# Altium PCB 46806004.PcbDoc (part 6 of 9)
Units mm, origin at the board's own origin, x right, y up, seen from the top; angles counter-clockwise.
Board outline 130 x 105 mm, 8 copper layers (Top Layer, P1-GND, L1-Signal, L2-Signal, L3-Signal, L4-Signal, P2-GND, Bottom Layer), stack 1.63 mm thick; 796 components, 496 nets, 2808 pads, 1195 vias.
Unrouted connection lines stored in the file: 1.
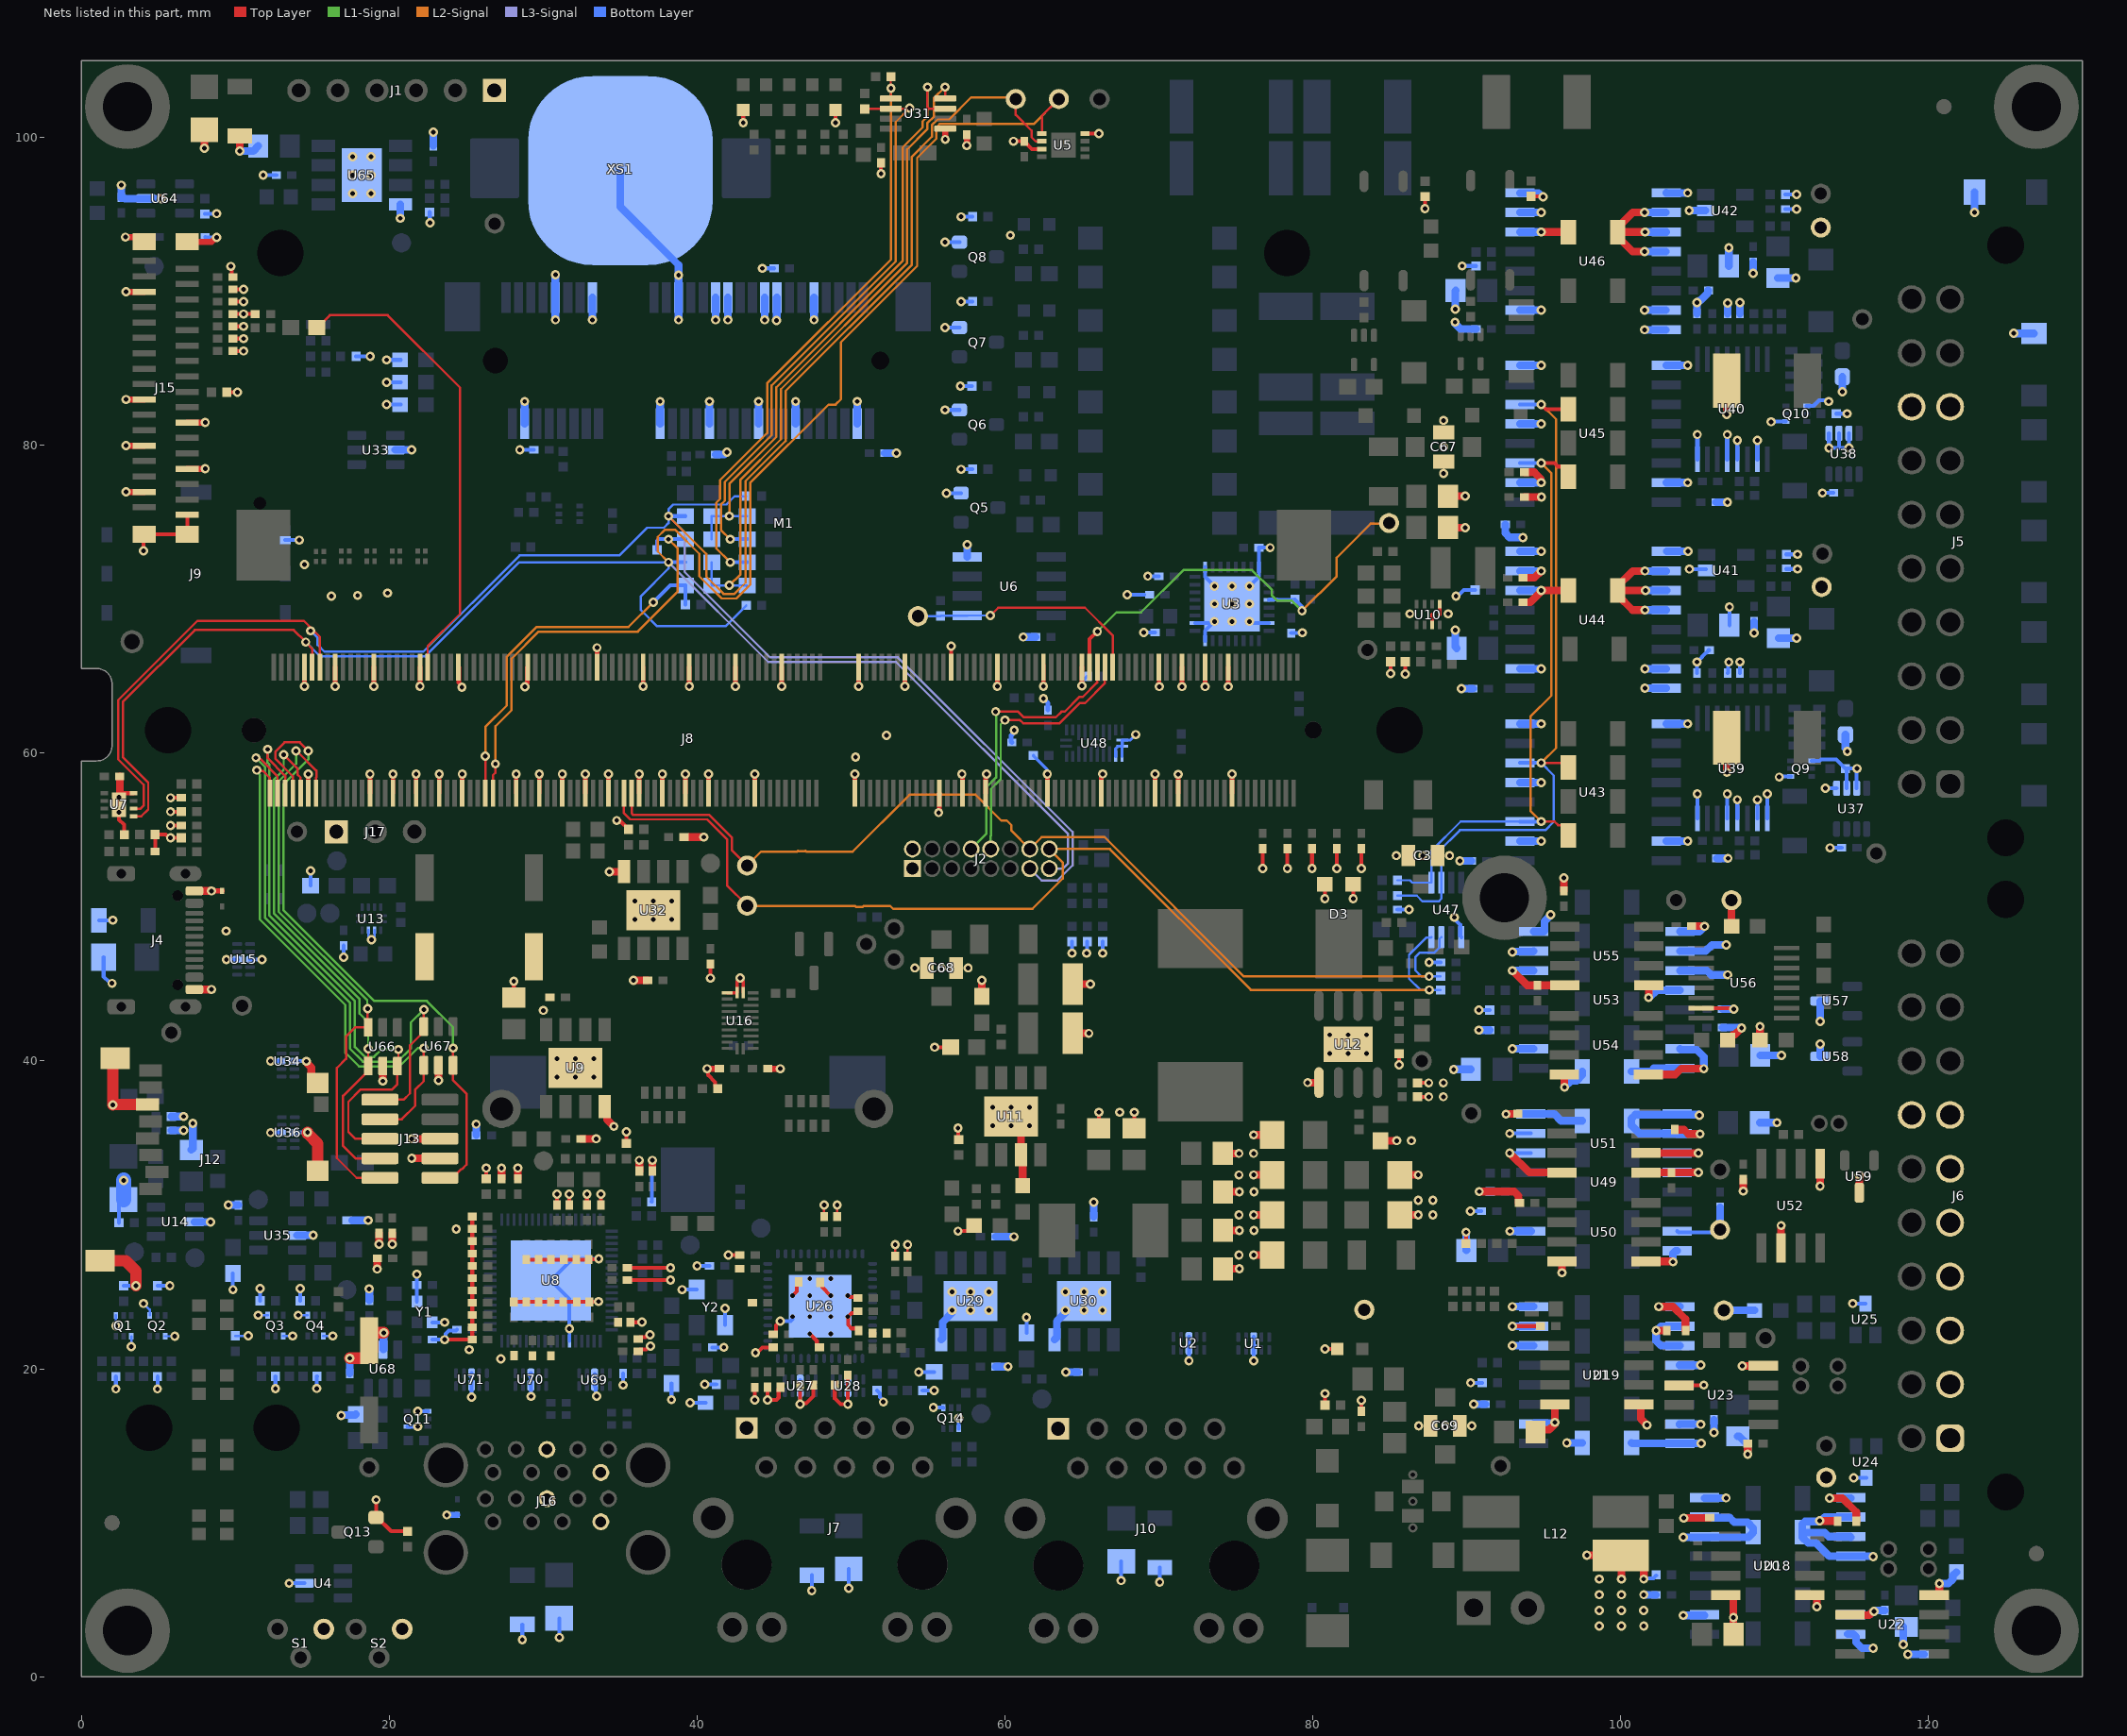
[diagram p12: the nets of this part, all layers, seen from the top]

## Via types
v1: diameter 0.6, hole 0.3, Top Layer to Bottom Layer, tented both sides, 1130 vias
v2: diameter 0.6, hole 0.3, Top Layer to Bottom Layer, 53 vias
v3: diameter 0.3, hole 0.3, Top Layer to Bottom Layer, 12 vias

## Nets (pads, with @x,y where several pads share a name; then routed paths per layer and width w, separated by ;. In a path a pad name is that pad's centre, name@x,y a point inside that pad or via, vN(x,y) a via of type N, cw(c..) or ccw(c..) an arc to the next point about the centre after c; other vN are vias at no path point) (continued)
GND: C2.1 C3.2 C4.1 C5.1 C6.1 C7.1 C8.1 C9.1 C10.1 C11.1 C12.1 C13.1 C14.1 C15.1 C16.1 C17.1 C18.1 C19.1 C20.2 C21.1 C22.1 C23.1 C24.1 C25.1 C26.1 C27.2 C28.1 C29.1 C30.1 C31.1 C32.1 C33.1 C34.2 C35.1 C36.1 C37.1 C38.1 C39.1 C40.1 C41.2 C42.1 C43.1 C44.1 C45.1 C46.1 C47.1 C48.2 C49.2 C50.1 C51.1 C52.1 C53.1 C54.2 C55.2 C56.1 C57.1 C58.1 C59.2 C60.2 C61.1 C62.1 C63.1 C64.1 C65.1 C66.1 C67.2 C68.2 C69.2 C70.1 C71.1 C72.1 C73.1 C74.1 C75.1 C76.1 C77.1 C78.1 C79.1 C81.2 C84.2 C86.1 C88.1 C89.1 C91.1 C92.1 C94.1 C95.1 C96.1 C97.2 C98.1 C99.1 C100.2 C101.2 C102.1 C103.2 C104.1 C106.1 C107.1 C108.1 C109.1 C111.1 C114.1 C115.1 C116.1 C117.2 C118.2 C119.2 C120.2 C133.1 C134.1 C135.1 C136.1 C137.1 C138.1 C139.1 C140.1 C141.1 C142.1 C143.1 C144.1 C145.1 C146.1 C147.1 C148.1 C149.1 C150.1 C151.1 C152.1 C153.1 C154.1 C155.1 C156.1 C157.1 C158.1 C159.1 C160.1 C161.1 C162.1 C163.1 C164.1 C165.1 C166.1 C167.1 C168.2 C169.2 C170.1 C171.1 C172.1 C173.1 C174.1 C175.1 C176.1 C177.1 C178.1 C179.1 C180.1 C181.1 C182.1 C207.1 C208.1 C209.1 C210.2 C211.2 C212.1 C213.1 C214.1 C215.1 C216.1 C217.1 C218.2 C219.2 C220.2 C226.1 C227.2 C228.2 C229.2 C239.1 C240.1 C241.1 C242.1 C243.1 C244.1 C245.1 C246.1 C247.1 C248.1 C249.1 C250.1 C251.1 C252.1 C253.1 C255.2 C257.1 C258.1 D3.1 D3.2 D4.2 D6.2 D18.2 D23.2 D26.2 D31.1 D32.2 J1.1 J2.1 J2.2 J4.A1/B12 J4.B1/A12 J5.15 J5.16 J7.1 J8.4 J8.9 J8.15 J8.18 J8.21 J8.26 J8.27 J8.29 J8.34 J8.35 J8.37 J8.40 J8.43 J8.50 J9.C5 J10.1 J12.6 J12.10 J12.11 J12.12 J12.13 J13.3 J13.5 J15.1 J15.4 J15.7 J15.10 J15.13 J15.16 J15.30 J15.SH1 J15.SH2 J15.SH3 J15.SH4 J16.L4 J16.L7 J16.U4 J16.U7 J17.1 L12.3 M1.10 M1.11 M1.18 M1.27 M1.28 M1.33 M1.39 M1.40 M1.45 M1.50 M1.51 M1.65 M1.68 M1.71 M1.77 M1.83 M1.86 M1.89 M1.97 M1.98 M1.103 M1.109 M1.110 M1.115 M1.122 M1.127 M1.134 M1.145 M1.146 M1.158 M1.167 M1.170 M1.173 M1.179 M1.182 M1.194 M1.195 M1.204 M1.209 M1.223 M1.224 M1.229 M1.230 M1.236 M1.242 M1.243 Q1.1 Q1.4 Q2.1 Q2.4 Q3.1 Q3.4 Q4.1 Q4.4 Q5.2 Q6.2 Q7.2 Q8.2 Q11.1 Q11.4 Q13.2 Q14.1 Q14.4 R3.2 R7.1 R20.2 R21.2 R26.1 R27.1 R29.2 R31.2 R32.1 R33.1 R34.1 R38.1 R40.1 R46.1 R49.1 R52.1 R54.1 R55.2 R57.1 R60.1 R62.1 R63.1 R66.2 R67.1 R70.1 R71.1 R74.1 R75.1 R78.1 R79.1 R81.1 R82.1 R84.1 R88.1 R89.1 R106.1 R107.1 R108.1 R109.1 R114.1 R116.1 R118.1 R122.2 R128.2 R130.2 R131.2 R150.1 R156.2 R176.1 R178.1 R185.1 R188.1 R192.1 R197.1 R198.1 R199.1 R202.1 R205.1 R206.1 R212.1 R214.2 R216.1 R236.1 R240.1 R244.2 R250.2 R256.1 R262.1 R263.1 R266.2 R268.2 R272.2 R273.1 S1.2 S2.2 U1.3 U1.8 U2.3 U2.8 U3.2 U3.9 U3.16 U3.23 U3.32 U3.33 U4.2 U5.4 U5.7 U6.4 U7.4 U7.9 U8.40 U8.69 U9.8 U9.9 U10.3 U10.5 U11.7 U11.9 U12.1 U12.9 U13.10 U13.11 U14.2 U15.3 U15.8 U16.11 U16.12 U16.13 U18.2 U18.6 U18.7 U18.8 U19.2 U19.6 U19.7 U19.8 U20.4 U21.4 U26.49 U27.3 U27.8 U28.3 U28.8 U29.8 U29.9 U30.8 U30.9 U31.1 U32.8 U32.9 U33.2 U34.3 U34.8 U35.2 U36.3 U36.8 U43.2 U43.5 U43.8 U44.2 U44.6 U44.7 U44.8 U45.2 U45.5 U45.8 U46.2 U46.6 U46.7 U46.8 U47.1 U48.11 U48.12 U48.13 U48.14 U49.2 U49.6 U49.7 U49.8 U50.4 U51.4 U53.2 U53.6 U53.7 U53.8 U54.4 U55.4 U64.2 U65.8 U65.9 U66.2 U67.2 U68.2 U69.3 U69.8 U70.3 U70.8 U71.3 U71.8 X1.1 XS1.1 Y1.2 Y1.4 Y2.2 Y2.4 | length 541.2
  Top Layer w0.15: C138.1@48.25,29.9 v1(48.25,30.65) ; C151.1@49.1,29.9 v1(49.1,30.65) ; C153.1@52.874,27.318 v1(52.874,28.068) ; C137.1@53.674,27.318 v1(53.674,28.068)
  Top Layer w0.2: U16.13@41.95,44.425 42.575,44.425 U16.12@42.6,44.45 42.6,45.2 v1(42.8,45.4) 43,45.2 U16.11@43,44.45
  Top Layer w0.25: v1(2.45,56.15) 2.45,55.675 2.775,55.35 2.775,54.725 R7.1@2.8,54.7 ; U7.9@2.675,57.225 2.525,57.225 v1(2.45,57.15) 2.45,57.4 U7.4@3.4,57.4 ; v1(4.05,73.142) 4.05,74.197 J15.SH2@4.081,74.228 J15.SH1@6.881,74.228 J15.1@6.881,75.478 ; C100.2@4.8,53.613 R52.1@4.8,54.713 5.492,54.713 5.705,54.5 v1(5.8,54.5) R54.1@6.5,54.5 ; v1(5.8,55.3) C101.2@6.5,55.3 ; v1(5.8,56.2) R57.1@6.5,56.2 ; v1(5.8,57.1) C103.2@6.5,57.1 ; R199.1@9.45,83.45 v1(10.15,83.45) ; v1(9.718,91.626) 9.784,91.56 9.784,90.994 C250.1@9.85,90.928 ; C247.1@9.85,86.128 v1(10.55,86.128) ; C249.1@9.85,86.928 v1(10.55,86.928) ; C251.1@9.85,87.728 v1(10.55,87.728) ; C248.1@9.85,88.528 v1(10.55,88.528) C245.1@11.3,88.528 ; C246.1@9.85,89.328 v1(10.55,89.328) ; C252.1@9.85,90.128 v1(10.55,90.128) ; v1(19.15,11.5) Q13.2@19.15,10.35 19.225,10.35 20.125,9.45 R263.1@21.2,9.45 ; v1(23.6,21.9) C49.2@25.4,21.9 C46.1@25.4,22.7 C40.1@25.4,23.5 C36.1@25.4,24.3 C50.1@25.4,25.1 C26.1@25.4,25.9 C53.1@25.4,26.7 C33.1@25.4,27.5 C30.1@25.4,28.3 C44.1@25.4,29.1 C47.1@25.4,29.9 ; M1.50@24.5,65.6 M1.50@24.525,65.575 ; 24.525,64.587 24.725,64.387 v1(24.725,64.293) ; R21.2@26.3,32.35 v1(26.3,33.05) ; C61.1@28.095,44.13 v1(28.095,45.182) ; C25.1@28.1,24.35 C29.1@28.9,24.35 C54.2@29.7,24.35 C35.1@30.5,24.35 C32.1@31.3,24.35 C42.1@32.2,24.35 C38.1@33,24.35 ; C61.1@28.21,44.13 C61.1@28.215,44.125 ; v1(28.825,64.31) 28.825,64.405 v1@28.975,64.555 ; C37.1@28.9,27.1 C31.1@29.7,27.1 C34.2@30.5,27.1 C24.1@32.95,27.1 32.974,27.124 33.592,27.124 v1(33.616,27.147) ; M1.68@28.975,65.575 M1.68@29,65.6 ; C56.1@30.9,30.65 v1(30.9,31.35) ; C60.2@31.7,30.65 v1(31.7,31.35) ; C57.1@32.85,30.65 v1(32.85,31.35) ; C38.1@33.012,24.362 33.014,24.364 33.595,24.364 v1(33.61,24.379) ; C52.1@33.75,30.65 v1(33.75,31.35) ; v1(34.78,55.628) 34.847,55.561 35.039,55.561 R150.1@35.55,55.05 ; R26.1@35.402,34.651 35.404,34.653 v1(35.404,35.4) ; C20.2@35.477,25.775 v1(38.275,25.775) ; C18.1@35.477,26.575 v1(38.275,26.575) ; C62.1@35.679,23.03 v1@36.412,23.03 ; C59.2@36.179,21.156 36.298,21.275 36.705,21.275 36.916,21.486 v1(36.975,21.486) ; C55.2@36.179,21.956 36.298,22.075 36.67,22.075 36.746,22.15 36.883,22.15 v1(36.95,22.217) ; v1(40.65,39.5) 40.702,39.448 40.702,39.098 41.175,38.625 41.175,38.375 R272.2@41.35,38.2 ; v1(40.865,45.385) C176.1@40.865,46.3 ; v1(42.029,27.4) C141.1@42.85,27.4 ; C154.1@42.775,26.503 C154.1@42.813,26.466 ; v1(43,100.95) D18.2@43,101.775 ; C147.1@43.475,24.425 C147.1@43.6,24.3 ; v1(43.75,17.979) C160.1@43.75,18.8 ; v1(43.8,21.05) 43.895,21.05 44.245,21.4 C146.1@44.95,21.4 ; C162.1@44.575,18.803 v1(44.575,17.982) 45.153,17.982 45.299,18.128 45.299,18.678 C164.1@45.424,18.803 ; C143.1@44.95,22.25 45,22.25 45.125,22.375 45.125,22.825 v1(45.4,23.1) ; v3(46.2,24.753) 46.2,24.767 46.475,25.042 46.475,25.525 C150.1@46.6,25.65 ; v1(46.688,17.708) v1@46.694,17.714 ; C136.1@46.7,18.95 46.694,18.944 v1@46.694,17.714 ; v3@47.331,22.265 47.783,21.813 47.783,21.525 47.908,21.4 C155.1@47.95,21.4 ; C133.1@47.55,18.95 47.55,18.232 47.084,17.767 46.747,17.767 v1@46.694,17.714 ; C140.1@48,25.625 48.125,25.5 48.125,25.307 v3@48.669,24.763 ; C148.1@48.95,18.95 48.95,18.083 49.325,17.708 v1(49.8,17.708) C152.1@49.8,19.6 ; v1(49,100.95) D6.2@49,101.775 ; v3(49.8,23.396) 49.81,23.387 49.81,22.866 50.047,22.628 50.375,22.628 50.5,22.503 C149.1@50.5,22.5 ; v3(49.8,24.753) 49.814,24.753 49.907,24.66 50.34,24.66 C145.1@50.4,24.6 ; v3@49.81,23.406 50.029,23.625 50.275,23.625 C134.1@50.4,23.75 ; v1(51.95,97.65) C173.1@51.95,98.35 ; v1(55.425,40.9) R32.1@56.475,40.9 ; M1.167@55.75,57.4 M1.167@55.76,57.41 ; M1.170@56.5,65.6 v1(56.5,66.95) v1@56.525,66.925 ; v1(56.95,28.95) 57.65,28.95 C81.2@58,29.3 ; v1(56.954,35.646) 56.977,35.623 56.977,34.923 R40.1@57,34.9 ; v1(60.55,99.75) C14.1@61.25,99.75 61.75,99.25 U5.7@62.4,99.25 ; M1.194@62.5,65.6 M1.194@62.5,65.739 ; U5.4@65.2,100.25 v1(66.1,100.25) ; C95.1@66.1,35.625 v1(66.1,36.675) ; C94.1@68.4,35.625 v1(68.4,36.675) ; M1.224@70,65.6 M1.224@70.013,65.588 ; v1@70.013,64.337 v1(70.025,64.325) ; v1(76.75,52.506) 76.75,53.45 ; v1(78.35,52.506) 78.35,53.45 ; v1(79.95,52.506) 79.95,53.45 ; v1(80.78,50.542) D3.2@80.78,51.486 ; R49.1@80.8,17.65 v1(80.8,18.4) ; v1(80.8,21.3) D4.2@81.575,21.3 ; v1(81.55,52.506) 81.55,53.45 ; v1(82.62,50.542) D3.1@82.62,51.486 ; C97.2@83.15,17.25 v1(83.15,17.95) ; v1(83.15,52.506) 83.15,53.45 ; v1(85.05,65.175) R27.1@85.05,65.912 ; v1(85.6,39.75) R46.1@85.6,40.478 ; v1(86,65.15) R38.1@86,65.95 ; R33.1@86.8,37.678 v1(87.528,37.678) ; R34.1@86.8,38.578 v1(87.528,38.578) ; v1(87.28,95.383) 87.288,95.391 87.288,96.146 R198.1@87.295,96.153 ; U10.3@87.75,68.325 87.75,69 ; 88.25,69 U10.5@88.25,69.675 ; R185.1@89.95,28.15 v1(89.95,28.887) ; v1(92.969,22.774) 92.979,22.784 C120.2@94.788,22.784 ; R197.1@94.175,96.173 94.187,96.162 94.938,96.162 v1(94.95,96.15)
  Top Layer w0.3: v1(14.5,64.35) M1.10@14.5,65.6 ; M1.11@14.75,57.4 v1(14.75,58.65) ; v1(16.5,64.35) M1.18@16.5,65.6 ; M1.27@18.75,57.4 v1(18.75,58.65) ; v1(19,64.35) M1.28@19,65.6 ; M1.33@20.25,57.4 v1(20.25,58.65) ; M1.39@21.75,57.4 v1(21.75,58.65) ; v1(22,64.35) M1.40@22,65.6 ; M1.45@23.25,57.4 v1(23.25,58.65) ; 24.525,64.587 M1.50@24.525,65.575 ; M1.51@24.75,57.4 v1(24.75,58.65) ; M1.65@28.25,57.4 v1(28.25,58.65) ; v1@28.975,64.555 M1.68@28.975,65.575 ; M1.71@29.75,57.4 v1(29.75,58.65) ; M1.77@31.25,57.4 v1(31.25,58.65) ; M1.83@32.75,57.4 v1(32.75,58.65) ; M1.86@33.5,65.6 v1(33.5,66.85) ; M1.89@34.25,57.4 v1(34.25,58.65) ; M1.97@36.25,57.4 v1(36.25,58.65) ; v1(36.5,64.35) M1.98@36.5,65.6 ; M1.103@37.75,57.4 v1(37.75,58.65) ; M1.109@39.25,57.4 v1(39.25,58.65) ; v1(39.5,64.35) M1.110@39.5,65.6 ; M1.115@40.75,57.4 v1(40.75,58.65) ; v1(42.5,64.35) M1.122@42.5,65.6 ; M1.127@43.75,57.4 v1(43.75,58.65) ; v1(45.5,64.35) M1.134@45.5,65.6 ; M1.145@50.25,57.4 v1(50.25,58.65) ; v1(50.5,64.35) M1.146@50.5,65.6 ; v1(53.5,64.35) M1.158@53.5,65.6 ; v1(55.697,56.137) v1(55.697,56.137) 55.7,56.139 55.75,56.139 M1.167@55.75,57.4 ; v1(57.2,58.65) 57.25,58.65 M1.173@57.25,57.4 ; M1.179@58.75,57.4 58.75,58.65 v1(58.8,58.65) ; v1(59.5,64.35) M1.182@59.5,65.6 ; v1(62.5,64.35) M1.194@62.5,65.6 ; M1.195@62.75,57.4 v1(62.75,58.65) ; v1(65,64.375) M1.204@65,65.6 ; M1.209@66.25,57.4 66.25,58.55 v1(66.354,58.654) ; M1.223@69.75,57.4 v1(69.75,58.65) ; v1@70.013,64.337 M1.224@70.013,65.588 ; M1.229@71.25,57.4 v1(71.25,58.625) ; v1(71.5,64.325) M1.230@71.5,65.6 ; v1(73,64.325) M1.236@73,65.6 ; v1(74.5,64.325) M1.242@74.5,65.6 ; M1.243@74.75,57.4 v1(74.75,58.65)
  Top Layer w0.35: v1(8.45,51.05) D32.2@9.15,51.05
  Top Layer w0.4: v1(2.868,93.528) 3.781,93.528 J15.SH3@4.081,93.228 ; v1(2.913,76.978) J15.4@4.081,76.978 ; v1(2.913,79.978) J15.10@4.081,79.978 ; v1(2.913,82.978) J15.16@4.081,82.978 ; v1(2.913,89.978) J15.30@4.081,89.978 ; J15.7@6.881,78.478 v1(8.05,78.478) ; J15.13@6.881,81.478 v1(8.05,81.478) ; J15.SH4@6.881,93.228 8.474,93.228 8.746,93.5 v1(8.8,93.5) ; v1(40.65,39.5) C114.1@41.45,39.5 ; C111.1@44.6,39.5 v1(45.4,39.5) ; v1(56.12,99.875) U31.1@56.12,100.575 ; v1(57.525,99.475) C167.1@57.525,100.175
  Top Layer w0.5: U7.9@2.5,57.2 C16.1@2.5,58.5 ; J4.B1/A12@7.35,44.65 v1(8.45,44.65) ; J4.A1/B12@7.35,51.05 v1(8.45,51.05) ; v1(8,99.3) C102.1@8,100.5 ; v1(10.3,99.125) R55.2@10.3,100.1 ; v1(14.625,39.987) 14.644,39.968 14.644,39.874 14.947,39.57 14.947,38.975 15.347,38.575 J12.10@15.363,38.575 ; v1@19.231,26.481 C21.1@19.231,27.181 ; v1(19.35,28.1) C161.1@19.35,28.8 ; v1(19.587,38.7) U66.2@19.587,39.675 ; v1(20.2,28.1) C157.1@20.2,28.8 ; v1(21.47,33.68) J13.3@23.3,33.68 ; v1(21.47,34.95) J13.5@23.3,34.95 ; v1(23.2,38.75) U67.2@23.2,39.725 ; C48.2@27.3,32.35 v1(27.3,33.05) ; C45.1@28.35,32.35 v1(28.35,33.05) ; C66.1@32.465,34.95 v1(33.454,34.95) ; U9.8@34.005,37.05 34.156,36.899 34.156,36.194 v1(34.6,35.75) ; v1(34.315,52.3) U32.8@35.26,52.3 ; v1(35.875,45.25) C174.1@36.79,45.25 ; C65.1@36.25,32.85 v1(36.25,33.55) ; C64.1@37.1,32.85 v1(37.1,33.55) ; 39.5,54.55 v1(40.445,54.55) ; R29.2@58.5,44.2 v1(58.5,45.25) ; C84.2@61.15,31.9 61.15,33.785 U11.7@61.035,33.9 61.035,35.235 v2(61.6,35.8) ; C73.1@64.4,41.8 v1(65.45,41.8) ; C77.1@64.4,45 v1(65.55,45) ; C92.1@74.15,34 v1(75.2,34) ; C96.1@74.175,26.5 v1(75.225,26.5) ; C98.1@74.175,29 v1(75.225,29) ; C99.1@74.175,31.5 v1(75.225,31.5) ; v1(76.15,27.4) C70.1@77.35,27.4 ; v1(76.15,30) C72.1@77.35,30 ; v1(76.15,32.6) C75.1@77.35,32.6 ; v1(76.15,35.2) C76.1@77.35,35.2 ; v1(79.667,38.6) U12.1@80.395,38.6 ; R31.2@84.4,34.828 v1(85.45,34.828) ; C78.1@85.65,30 v1(86.85,30) ; C79.1@85.65,32.6 v1(86.85,32.6) ; C71.1@88.775,76.7 v1(89.9,76.7) ; C74.1@88.777,74.654 v1(89.902,74.654) ; v1@90.832,31.521 93.079,31.521 93.372,31.228 93.372,30.785 C219.2@93.422,30.785 ; v1(92.55,36.55) 92.567,36.567 93.305,36.567 C220.2@93.322,36.585 ; v1(92.791,34.027) 94.06,32.758 U51.4@96.191,32.758 ; v1(92.969,45.875) 92.969,45.872 93.917,44.924 C229.2@94.594,44.924 U55.4@96.37,44.924 ; C88.1@93.65,69.8 94.134,69.8 94.812,70.478 94.812,70.55 v1(94.831,70.569) 96.594,70.569 R256.1@96.6,70.563 ; C86.1@93.65,71.4 94.392,71.4 v1(94.831,71.839) ; C89.1@93.75,76.65 v1(94.85,76.65) ; C91.1@93.75,78.25 94.387,78.25 94.812,77.825 94.812,77.598 v1(94.831,77.579) ; C116.1@94.475,15.9 94.624,16.049 95.354,16.049 95.712,16.407 95.712,16.506 v1(95.731,16.525) ; v1(94.831,93.862) 94.834,93.859 96.594,93.859 R262.1@96.6,93.853 ; v1@95.72,16.437 U21.4@95.72,17.695 ; v1(96.191,26.245) U50.4@96.191,26.982 ; C228.2@96.3,51.05 v1(96.3,51.9) ; U54.4@96.347,39.124 96.347,38.303 v1(96.35,38.3) ; v1(97.8,7.9) 99.99,7.9 L12.3@100.01,7.88 ; v1(100.05,6.35) 100.05,7.84 L12.3@100.01,7.88 ; v1(101.5,6.35) 101.5,7.14 100.76,7.88 L12.3@100.01,7.88 ; v1(104.099,10.309) v1(104.099,10.309) C119.2@105.78,10.31 ; C115.1@107.325,2.71 v1(107.325,3.848) 107.325,5.141 U20.4@107.439,5.255
  Top Layer w0.75: J12.12@1.213,27.025 2.875,27.025 3.55,26.35 v1(3.55,25.4) ; v1(2.05,37.15) 2.05,40.012 J12.11@2.213,40.175 ; v1@2.085,37.185 J12.6@4.303,37.185 ; v1(14.7,35.375) 14.7,35.3 15.363,34.637 J12.13@15.363,32.875 ; v1(17.45,20.7) 18.481,20.7 18.919,21.137 18.919,22.35 v1(19.65,22.35)
  Bottom Layer w0.15: v1(2.25,22.8) Q1.1@2.25,23.475 ; v1(3.25,21.45) Q1.4@3.25,22.125 ; v1(4.05,24.25) 4.45,23.85 Q2.1@4.45,23.475 ; Q2.4@5.45,22.125 v1(6.075,22.125) ; R82.1@10,22.15 v1(10.85,22.15) ; v1(11.489,23.49) Q3.1@12.114,23.49 ; Q3.4@13.114,22.14 v1(13.739,22.14) ; v1(14.089,23.49) Q4.1@14.714,23.49 ; Q4.4@15.714,22.14 v1(16.339,22.14) ; U13.11@18.65,48.5 18.65,48.075 v1(18.85,47.875) 19.05,48.075 U13.10@19.05,48.5
  Bottom Layer w0.2: U8.40@31.711,21.8 v1(31.711,22.606) ; R273.1@61.85,59.85 61.85,59.826 62.75,58.926 v1(62.75,58.65) ; v1(65,64.375) 65.077,64.452 65.077,64.72 R84.1@65.35,64.993 ; U48.14@67.2,59.8 67.2,60.3 67.35,60.45 U48.12@67.625,60.45 ; U48.13@67.6,59.8 67.6,60.425 U48.12@67.625,60.45 ; v1(68.492,61.208) 68.5,61.2 68.15,60.85 U48.11@67.625,60.85 U48.12@67.625,60.45
  Bottom Layer w0.25: R66.2@1.15,49.15 v1(2.05,49.15) ; C109.1@1.45,46.75 1.45,45.5 1.833,45.117 1.933,45.117 v1(2,45.05) ; v1(2.25,18.7) R70.1@2.25,19.5 ; R62.1@2.45,29.5 2.45,30.7 C107.1@2.75,31 ; R67.1@2.75,25.4 v1(3.55,25.4) ; v1(2.868,93.528) C244.1@4.05,93.528 ; v1(4.95,18.7) R74.1@4.95,19.5 ; R71.1@4.95,25.4 v1(5.75,25.4) ; R206.1@8.031,95.028 8.042,95.039 8.789,95.039 v1(8.8,95.05) ; C243.1@8.05,93.528 8.064,93.514 8.786,93.514 v1(8.8,93.5) ; v1(9.42,46.6) U15.3@10.17,46.6 ; v1(9.85,25.15) R156.2@9.85,26.2 ; U15.8@10.987,46.6 v1(11.738,46.6) ; R75.1@11.614,24.415 v1(11.614,25.215) ; v1(11.817,97.547) C239.1@12.675,97.547 ; v1(12.3,35.35) U36.8@13.008,35.35 ; v1(12.3,40) 12.971,40 U34.8@12.983,39.987 ; v1(12.614,18.715) R78.1@12.614,19.515 ; J9.C5@13.245,73.84 v1(14.153,73.84) ; v1(13.5,6.075) U4.2@14.495,6.075 ; U34.3@13.8,39.987 v1(14.625,39.987) ; U36.3@13.825,35.35 13.838,35.363 14.687,35.363 v1(14.7,35.375) ; R79.1@14.214,24.415 v1(14.214,25.215) ; R60.1@14.9,51.4 v1(14.9,52.35) ; v1(15.301,18.732) 15.308,18.739 15.308,19.508 R81.1@15.314,19.515 ; v1(17.05,46.75) C106.1@17.05,47.497 ; R202.1@17.85,85.775 v1(18.772,85.775) ; v1(19.84,82.65) C177.1@20.7,82.65 C177.1@20.75,82.65 ; v1(19.84,84.1) C178.1@20.7,84.1 C178.1@20.75,84.1 ; v1(19.84,85.55) C179.1@20.7,85.55 C179.1@20.75,85.55 ; Q11.1@21.175,16.25 v1(21.85,16.25) ; Y1.4@21.8,24.375 21.8,25.6 v1(21.8,26.15) ; v1(21.861,17.25) Q11.4@22.525,17.25 ; R205.1@22.625,95.15 22.637,95.137 22.637,94.463 v1(22.65,94.45) ; C23.1@22.8,21.9 v1(23.6,21.9) 23.667,21.967 23.667,22.267 23.885,22.485 24.335,22.485 C43.1@24.4,22.55 ; Y1.2@22.8,23.025 v1(23.6,23.025) ; v1(25.35,18.175) U71.3@25.35,18.925 U71.8@25.35,19.742 ; v1(28.49,79.7) C175.1@29.4,79.7 ; v1(28.65,2.4) R214.2@28.65,3.4 ; U70.8@29.2,19.742 U70.3@29.2,18.925 29.213,18.912 29.213,18.226 v1(29.225,18.214) ; v1(31.05,2.55) C257.1@31.05,3.8 ; v1(31.711,22.606) 31.711,24.547 U8.69@30.511,25.747 31.911,27.147 v1(33.616,27.147) ; U69.3@33.35,19.675 U69.8@33.35,18.858 33.416,18.792 33.416,18.288 v1(33.482,18.222) ; v1(35.2,18.95) C28.1@35.2,19.7 ; R212.1@37.05,30.85 37.075,30.875 37.075,33.525 v1(37.1,33.55) ; v1(38.341,18) R20.2@38.341,19.05 ; v1(39.031,25.15) Y2.2@39.975,25.15 ; v1(39.55,17.8) C156.1@40.55,17.8 ; v1(40,26.7) C142.1@40.8,26.7 ; v1@40.511,19 R122.2@41.25,19 ; C139.1@41,21.4 v1@41.739,21.4 ; Y2.4@41.825,22.85 v1(41.825,23.925) ; v1(44.25,91.5) C172.1@45,91.5 ; v1(45.4,23.1) 46.075,23.1 46.2,23.225 v3(46.2,23.396) ; v1(46.688,17.708) 46.694,17.714 46.694,18.452 U27.8@46.7,18.458 U27.3@46.7,19.275 ; v1(47.45,5.6) R131.2@47.45,6.6 ; v1(49.8,17.708) U28.8@49.8,18.458 U28.3@49.8,19.275 ; v1(49.85,5.75) C163.1@49.85,7 ; R268.2@51.7,18.6 51.875,18.425 51.875,18.17 52.1,17.945 v1(52.1,17.85) ; v1(54.4,19.8) R128.2@55.4,19.8 ; R266.2@54.65,18.6 v1(55.4,18.6) ; v1(55.35,17.5) 55.363,17.488 55.987,17.488 Q14.1@56,17.475 ; v1@56.1,93.19 v1(56.104,93.194) 57.043,93.194 Q8.2@57.047,93.199 ; v1(56.108,82.299) Q6.2@57.047,82.299 ; v1(56.108,87.649) Q7.2@57.047,87.649 ; v1@56.208,76.899 Q5.2@57.147,76.899 ; Q14.4@57,16.125 v1(57,16.8) ; v1@57.108,83.849 R107.1@57.847,83.849 ; v1(57.15,78.44) 57.154,78.444 57.893,78.444 R106.1@57.897,78.449 ; v1@57.158,89.349 R108.1@57.897,89.349 ; v1@57.158,94.849 R109.1@57.897,94.849 ; R130.2@61.4,22.35 v1(61.4,23.35) ; v1@64.35,47.011 R118.1@64.35,47.75 ; v1(65.304,47.007) 65.327,47.03 65.327,47.727 R114.1@65.35,47.75 ; v1@66.35,47.011 R116.1@66.35,47.75 ; v1(67.55,6.25) C2.1@67.55,7.5 ; v1(67.95,70.3) 69.05,70.3 ; v1(69.025,67.85) C11.1@69.75,67.85 ; v1(69.275,71.5) C9.1@70,71.5 ; v1@70.025,64.255 v1(70.025,64.325) ; v1(70.05,6.15) R3.2@70.05,7.1 ; v1(71.95,20.533) U2.3@71.95,21.283 U2.8@71.95,22.1 ; U3.2@72.35,68.45 U3.33@73.5,68.45 ; U3.32@73,67.3 73,67.95 U3.33@73.5,68.45 ; U3.9@73,72.1 73,71.45 v2(73.607,70.843) ; v2(73.607,68.557) U3.33@73.5,68.45 ; v2(75.893,68.557) 76,68.45 U3.23@77.15,68.45 ; v2(75.893,70.843) 76.5,71.45 U3.16@76.5,72.1 C13.1@76.5,73.35 v1(77.225,73.35) ; v1(76.162,20.52) U1.3@76.163,21.27 U1.8@76.163,22.087 ; C10.1@78.6,67.8 78.613,67.812 79.312,67.812 v1(79.325,67.825) ; C209.1@85.5,49.845 v1(86.25,49.845) ; v1(87.55,46.4) C216.1@88.3,46.4 ; v1(89.2,49.335) 89.2,49.24 89.575,48.865 89.575,48.125 U47.1@89.65,48.05 ; v1(89.3,70.2) 89.395,70.2 89.795,70.6 R176.1@90.55,70.6 ; v1(89.696,91.648) 89.7,91.653 R178.1@90.6,91.653 ; v1@90.238,30.25 C218.2@90.95,30.25 ; v1(90.25,19.1) R89.1@91,19.1 ; v1@90.788,43.307 R192.1@91.5,43.307 ; v1(90.809,31.521) R188.1@91.522,31.523 ; v1@92.792,34.028 U49.6@94.172,34.028 ; v1@92.792,35.298 U49.7@94.172,35.298 ; v1(101.5,6.35) 101.54,6.39 101.735,6.39 101.75,6.405 102.125,6.405 R88.1@102.3,6.58 ; D26.2@122.985,96.45 D26.2@123.015,96.42 ; v1(125.525,87.275) v1@125.535,87.265
  Bottom Layer w0.3: C213.1@60.45,60.7 60.4,60.75 60.4,61.15 60.6,61.35 v1(60.6,61.5) ; v1(62.5,63.55) 62.8,63.25 C215.1@62.8,62.8
  Bottom Layer w0.4: v1(23.746,10.512) D31.1@24.421,10.512
  Bottom Layer w0.5: C241.1@2.6,96.111 v1(2.6,96.9) ; C241.1@2.611,96.1 2.611,96.05 2.818,96.05 2.84,96.028 v1(5.2,96.028) ; C108.1@5.85,35.5 v1(6.65,35.5) ; R63.1@5.85,36.4 v1(6.65,36.4) ; C104.1@7.15,34.225 7.25,34.325 v1(7.25,35.95) ; U14.2@7.36,29.55 v1(8.4,29.55) ; v1(9.55,30.65) C182.1@10.2,30.65 ; v1(10.3,99.125) 11.175,99.125 C240.1@11.5,99.45 ; U35.2@14.026,28.681 v1(15.066,28.681) ; v1(16.881,16.975) 16.9,16.994 17.775,16.994 R216.1@17.831,17.05 ; C258.1@17.45,19.7 v1(17.45,20.7) ; 17.6,29.65 v1(18.64,29.65) ; v1(18.7,25.2) 18.711,25.189 C253.1@18.711,24.45 ; U68.2@19.611,21.255 19.631,21.274 19.631,22.331 v1(19.65,22.35) ; U33.2@20.405,79.7 v1(21.455,79.7) ; v1(20.725,94.745) U65.8@20.725,95.645 ; C242.1@22.875,99.45 v1(22.875,100.35) ; C39.1@25.65,35.2 v1(25.65,35.9) ; J8.4@28.8,81.4 v1(28.8,82.85) ; v1(30.8,88.15) J8.9@30.8,89.6 v1(30.8,91.091) ; v1(33.2,88.15) J8.15@33.2,89.6 ; XS1.1@35.02,97.85 35.02,95.495 38.8,91.715 v1(38.8,91.05) J8.21@38.8,89.6 v1(38.8,88.15) ; J8.18@37.6,81.4 v1(37.6,82.85) ; J8.26@40.8,81.4 v1(40.8,82.85) ; C171.1@41.2,79.4 41.773,79.4 41.923,79.55 v1(41.95,79.55) ; v1(41.2,88.15) J8.27@41.2,89.6 ; v1(42,88.15) J8.29@42,89.6 ; J8.34@44,81.4 v1(44,82.85) ; v1(44.4,88.15) J8.35@44.4,89.6 ; v1(45.154,88.104) 45.177,88.127 45.177,89.577 J8.37@45.2,89.6 ; J8.40@46.4,81.4 v1(46.4,82.85) ; v1(47.6,88.15) J8.43@47.6,89.6 ; J8.50@50.4,81.4 v1(50.4,82.85) ; C170.1@52.2,79.5 v1(52.95,79.5) ; U29.8@55.86,21.9 55.947,21.987 55.947,23.027 56.565,23.644 v2(56.565,23.8) ; U6.4@57.556,72.751 v1(57.556,73.551) ; C165.1@59.4,20.15 v1(60.2,20.15) ; C158.1@59.4,28.595 60.566,28.595 v1(60.579,28.582) ; v1(61.186,67.546) C15.1@61.986,67.546 ; U30.8@63.23,21.9 63.381,22.051 63.381,22.692 63.384,22.695 63.384,23.093 63.935,23.644 v2(63.935,23.8) ; v1(63.95,19.8) C166.1@64.75,19.8 ; C159.1@65.77,29.88 v1(65.77,30.83) ; v1(89.15,39.45) 89.168,39.468 C226.1@90.275,39.468 ; v1(89.236,88.003) 89.236,87.914 89.597,87.553 C211.2@90.6,87.553 ; v1(89.25,68) 89.25,66.922 C212.1@89.354,66.818 ; v1(89.25,88.85) 89.25,90.028 C214.1@89.275,90.053 ; v1(89.55,53) C207.1@90.3,53 ; v1(89.65,64.2) C210.2@90.4,64.2 ; v1(89.95,28.887) 89.95,27.725 C217.1@89.975,27.7 ; v1(90.45,17.7) C118.2@91.2,17.7 ; v1(90.787,42.005) C227.2@91.5,42.007 ; C208.1@92.5,74.853 92.5,74.3 92.783,74.017 93.633,74.017 v1(93.65,74) ; v1(92.55,36.55) 92.568,36.568 U49.8@94.172,36.568 95.682,36.568 96.132,36.118 R244.2@97.5,36.118 ; v1(92.8,28.948) U49.2@94.172,28.948 ; v1(92.969,45.875) v1(92.969,45.875) 94.349,45.874 U53.6@94.35,45.873 ; v1(92.969,47.075) 93.003,47.109 94.316,47.109 U53.7@94.35,47.143 ; v1@92.97,21.505 U19.6@94.35,21.505 ; v1@92.97,22.775 U19.7@94.35,22.775 ; v1@92.97,24.045 U19.8@94.35,24.045 ; v1(92.969,40.792) U53.2@94.35,40.793 ; U43.2@93.45,54.288 v1@94.83,54.288 ; U43.5@93.45,58.098 v1@94.83,58.098 ; U43.8@93.45,61.908 v1@94.83,61.908 ; U44.2@93.45,65.488 v1(94.831,65.489) ; U44.6@93.45,70.568 v1(94.831,70.569) ; U44.7@93.45,71.838 v1(94.831,71.839) ; U44.8@93.45,73.108 v1(94.831,73.109) ; U45.2@93.45,77.578 v1(94.831,77.579) ; U45.5@93.45,81.388 v1(94.831,81.389) ; U45.8@93.45,85.198 v1(94.831,85.199) ; U46.2@93.45,88.778 v1(94.831,88.779) ; U46.6@93.45,93.858 93.452,93.86 94.829,93.86 v1(94.831,93.862) ; U46.8@93.45,96.398 94.642,96.398 94.89,96.15 v1(94.95,96.15) ; U46.7@93.452,95.13 v1@94.829,95.13 ; U19.2@94.35,16.425 94.4,16.475 95.654,16.475 95.704,16.525 v1(95.731,16.525) ; U53.8@94.35,48.413 95,48.413 95.05,48.463 95.05,49.069 95.456,49.475 v1(95.456,49.502) ; v1(96.35,38.3) 96.771,38.721 97.125,38.721 97.5,39.096 R250.2@97.5,39.318 ; v1(96.5,15.2) R240.1@97.5,15.2 ; v1(101.5,5.33) C117.2@102.29,5.33 ; v1(104.069,3.984) U18.2@105.45,3.985 ; v1(104.069,9.064) 108.305,9.065 108.6,9.36 108.6,9.66 108.225,10.035 107.385,10.035 107.085,10.335 U18.7@105.45,10.335 ; v1(104.099,10.309) U18.7@105.48,10.31 ; U18.8@105.45,11.605 105.456,11.611 106.838,11.611 v1(106.843,11.617) ; v1@122.985,95.135 D26.2@122.985,96.45 ; v1@125.535,87.265 D23.2@126.85,87.265
  Bottom Layer w1: C107.1@2.75,31 v1(2.75,32.25)
  other v1: 98.6,3.29 100.05,3.29 101.5,3.29 98.6,4.31 100.05,4.31 101.482,4.31 98.6,5.33 100.05,5.33 98.6,6.35 40.507,18.996 27.25,20.65 25.2,21.25 41.743,21.404 92.969,21.504 36.417,23.036 92.969,24.044 19.225,26.487 75.2,27.4 76.175,29 24.356,29.088 75.2,30 87.8,30 90.237,30.249 86.85,30.95 87.8,30.95 76.175,31.5 75.2,32.6 76.15,34 86.4,34.828 92.791,35.297 67.45,36.675 88.478,37.678 88.478,38.578 30.015,43.292 90.787,43.305 64.354,47.007 66.354,47.007 9.4,48.45 94.831,54.289 94.831,58.099 50.3,59.75 52.3,61.15 94.831,61.909 86.3,69.05 88.8,69.05 16.25,70.2 17.95,70.25 19.9,70.4 14.5,72.25 56.204,76.894 57.104,83.844 57.154,89.344 60.354,93.644 57.154,94.844 94.831,95.132 122.975,95.125
  other v2: 57.765,23.8 58.965,23.8 65.135,23.8 66.335,23.8 56.565,25 57.765,25 58.965,25 63.935,25 65.135,25 66.335,25 59.2,35.8 60.4,35.8 59.2,37 60.4,37 61.6,37 30.9,38.95 32.1,38.95 33.3,38.95 30.9,40.15 32.1,40.15 33.3,40.15 81.1,40.5 82.3,40.5 83.5,40.5 81.1,41.7 82.3,41.7 83.5,41.7 35.965,49.2 37.165,49.2 38.365,49.2 35.965,50.4 37.165,50.4 38.365,50.4 74.75,68.557 73.607,69.7 74.75,69.7 75.893,69.7 74.75,70.843 17.625,96.35 18.825,96.35 17.625,97.55 18.825,97.55 17.625,98.75 18.825,98.75
  other v3: 47.322,22.275 48.679,22.275 47.322,23.396 48.679,23.396 47.322,24.753 48.679,24.753 47.322,25.875 48.679,25.875
GND_232: C230.2 C231.2 C232.2 C233.1 C236.1 C237.1 C238.1 J6.13 J6.14 R250.1 U53.9 U53.10 U53.11 U53.12 U53.15 U53.16 U54.5 U55.5 U56.15 U57.3 U58.3 X78.1 | length 34.5
  Top Layer w0.25: U56.15@105.225,43.443 107.17,43.443 107.242,43.37 v1(107.337,43.37) ; v1@105.432,48.768 v1(105.45,48.75)
  Top Layer w0.5: U54.5@101.808,39.124 103.551,39.124 103.927,39.5 v1(105.4,39.5) ; v1(101.811,44.122) 101.82,44.131 101.82,44.914 U55.5@101.831,44.924 ; C231.2@104.6,48.768 v1@105.432,48.768 ; C237.1@106.95,41.368 107.3,41.718 107.418,41.718 v1(107.85,42.15) ; C236.1@107.2,48.768 X78.1@107.2,50.45 ; C238.1@109.05,41.368 v1(109.05,42.25)
  Bottom Layer w0.25: v1@107.831,42.169 v1(107.85,42.15)
  Bottom Layer w0.5: R250.1@100.7,39.318 101.941,39.318 102.146,39.523 U53.16@103.85,39.523 103.873,39.5 v1(105.4,39.5) 105.4,40.284 104.941,40.743 103.9,40.743 U53.15@103.85,40.793 ; v1(101.811,44.122) 101.856,44.122 102.337,44.603 U53.12@103.85,44.603 ; U53.11@103.85,45.873 105.6,45.873 105.873,45.6 v1(106.95,45.6) ; U53.10@103.85,47.143 105.518,47.143 105.925,47.55 v1(106.85,47.55) ; U53.9@103.85,48.413 105.113,48.413 v1(105.45,48.75) ; C230.2@106.611,42.169 v1@107.831,42.169 ; C232.2@106.624,43.369 v1@107.336,43.369 ; C233.1@109.063,40.368 v1@110.443,40.368 ; U58.3@112.95,40.3 v1(112.95,41.1) ; v1(112.95,42.567) U57.3@112.95,43.9
  other v1: 110.444,40.369
GND_485: C221.2 C222.2 C223.2 C224.1 C225.2 J6.9 J6.11 R244.1 U49.9 U49.10 U49.11 U49.12 U49.15 U49.16 U50.5 U51.5 U51.6 U52.2 U52.5 U59.3 X70.1 | length 33.3
  Top Layer w0.25: X70.1@106.448,29.498 X70.1@106.45,29.5
  Top Layer w0.5: U50.5@101.652,26.982 103.367,26.982 v1(103.4,26.95) ; U51.5@101.652,32.758 v1(105.053,32.759) v1(105.053,32.759) ; U51.6@101.652,34.028 v1(105.053,34.029) v1(105.053,34.029) ; C222.2@103.522,35.563 103.522,35.54 104.11,35.54 104.386,35.264 v1(105.153,35.264) ; v1(107.95,31.55) C225.2@107.95,32.3 ; U52.2@110.415,27.869 v1@110.415,29.309 ; v1(112.947,31.883) 112.951,31.887 112.951,33.327 U52.5@112.955,33.33 ; U59.3@115.5,31.45 v1(115.5,32.6)
  Bottom Layer w0.25: U49.15@103.672,28.948 103.76,28.859 106.259,28.859 X70.1@106.45,29.05 ; U49.12@103.672,32.758 v1(105.053,32.759) ; U49.11@103.672,34.028 v1(105.053,34.029)
  Bottom Layer w0.5: v1(103.4,26.95) 103.4,27.503 103.575,27.678 U49.16@103.672,27.678 ; U49.9@103.622,36.518 100.95,36.518 100.7,36.268 100.7,35.818 101.22,35.298 U49.10@103.672,35.298 ; U49.10@103.672,35.263 v1@105.152,35.263 ; U49.9@103.722,36.518 105.05,36.518 v1(105.1,36.468) ; X70.1@106.45,29.5 C223.2@106.45,30.488 ; C224.1@109.025,36 v1(110.15,36)
  other v1: 110.423,29.317
GND_AIN1: C183.2 C190.1 C191.1 C194.2 C195.1 C197.1 C199.1 C200.1 C203.1 C205.2 JP1.1 PTC5.2 Q9.1 Q9.4 R167.1 R175.1 R256.2 U37.1 U37.2 U37.3 U39.1 U39.2 U39.4 U39.5 U39.8 U41.2 U43.9 U43.15 U44.9 U44.10 U44.11 U44.12 U44.15 U44.16 X59.1 | length 46.1
  Top Layer w0.5: v1(101.569,69.297) 100.766,69.297 99.8,70.263 R256.2@99.8,70.563 ; v1(101.569,71.837) 100.774,71.837 99.8,70.863 R256.2@99.8,70.563 ; v1(101.607,70.569) 99.806,70.569 R256.2@99.8,70.563 ; PTC5.2@106.884,61 106.9,60.984 v1(106.9,58.75)
  Bottom Layer w0.25: v1(104.469,71.961) U41.2@105.532,71.961 ; C197.1@104.95,65.2 v1(104.95,65.928) 104.979,65.928 105.3,66.25 105.3,66.283 105.707,66.69 C205.2@105.757,66.69 ; U39.8@104.975,55.75 v1(104.975,57.35) ; U39.5@106.925,55.75 v1(106.925,57.35) ; C195.1@106.95,65.2 106.987,65.237 106.987,65.885 v1(107.023,65.922) ; C200.1@107.06,68.318 v1(107.06,69.49) ; U39.4@107.575,55.75 v1(107.575,56.975) ; C199.1@107.75,65.2 v1(107.75,65.928) ; U39.2@108.875,55.75 v1(108.875,56.975) ; U39.1@109.525,55.75 v1(109.525,57.35) ; v1(110.3,58.45) 110.35,58.5 Q9.1@111.05,58.5 ; C190.1@110.76,71.965 v1(111.488,71.965) ; R167.1@110.76,72.915 v1(111.488,72.915) ; Q9.4@112.4,59.5 112.909,59.5 113.006,59.597 114.003,59.597 114.675,58.925 U37.2@114.675,57.727 ; v1@113.302,57.726 U37.1@114.014,57.726 ; v1(113.6,53.85) C183.2@114.35,53.85 ; R175.1@114.601,59 v1(115.35,59) 115.325,58.975 U37.3@115.325,57.727
  Bottom Layer w0.5: v1@101.57,64.218 U44.16@102.95,64.218 ; v1@101.57,65.488 U44.15@102.95,65.488 ; v1@101.57,69.298 U44.12@102.95,69.298 ; v1@101.57,71.838 U44.10@102.95,71.838 ; v1(101.607,70.569) U44.11@102.988,70.57 ; U43.15@102.969,54.289 v1@104.349,54.289 ; U43.9@102.969,61.909 v1@104.349,61.909 ; U44.9@102.987,73.111 102.988,73.11 104.368,73.11 v1(104.369,73.111) ; C203.1@106.254,53.167 106.965,53.167 v1(106.967,53.168) ; v1(108.66,67.815) C194.2@108.66,68.543 ; C191.1@110.25,67.475 v1(111.428,67.475) ; JP1.1@114.6,61.2 114.6,60.332 114.719,60.213 v1(114.719,60.119)
  other v1: 104.35,54.29 113.301,57.725 104.35,61.91 101.569,64.217 101.569,65.487
GND_AIN2: C184.2 C189.1 C192.1 C193.2 C196.1 C198.1 C201.1 C202.1 C204.1 C206.2 JP2.1 PTC6.2 Q10.1 Q10.4 R166.1 R174.1 R262.2 U38.1 U38.2 U38.3 U40.2 U40.4 U40.5 U40.8 U42.2 U45.9 U45.15 U46.9 U46.10 U46.11 U46.12 U46.15 U46.16 X58.1 | length 44.4
  Top Layer w0.5: v1(101.55,92.586) 100.767,92.586 99.8,93.553 R262.2@99.8,93.853 ; v1(101.55,95.126) 100.773,95.126 99.8,94.153 R262.2@99.8,93.853 ; v1(101.588,93.858) 99.805,93.858 R262.2@99.8,93.853 ; v1(106.884,82) PTC6.2@106.884,84.2 PTC6.2@106.884,84.234
  Bottom Layer w0.25: v1(109.775,81.528) 109.8,81.553 Q10.1@110.725,81.553 ; C189.1@110.7,95.35 v1(111.428,95.35) ; R166.1@110.7,96.3 v1(111.428,96.3) ; Q10.4@112.075,82.553 112.511,82.553 112.883,82.925 113.188,82.925 113.197,82.915 113.442,82.915 v1(113.509,82.848) ; v1(113.1,76.9) 113.111,76.911 113.814,76.911 C184.2@113.825,76.921 ; U38.1@113.525,80.78 v1(113.525,79.83) 114.175,79.83 ; R174.1@114,82.053 v1@114.712,82.053 ; U38.2@114.175,80.78 114.175,79.83 ; U38.3@114.825,80.78 v1(114.825,79.83) 114.175,79.83
  Bottom Layer w0.3: U40.8@104.975,79.1 v1(104.975,80.7) ; U40.5@106.925,79.1 v1(106.925,80.7) ; U40.4@107.575,79.1 v1(107.575,80.325) ; U40.2@108.875,79.1 v1(108.875,80.325)
  Bottom Layer w0.5: v1@101.551,87.507 U46.16@102.931,87.507 ; v1@101.551,88.777 U46.15@102.931,88.777 ; v1@101.551,92.587 U46.12@102.931,92.587 ; v1@101.551,95.127 U46.10@102.931,95.127 ; v1@101.589,93.859 U46.11@102.969,93.859 ; U46.9@102.968,96.4 102.969,96.399 104.349,96.399 v1(104.35,96.4) ; U45.15@102.969,77.579 v1@104.349,77.579 ; U45.9@102.969,85.199 v1@104.349,85.199 ; v1(104.45,95.25) U42.2@105.513,95.25 ; C196.1@104.95,88.55 v1(104.95,89.278) 104.977,89.278 105.102,89.403 105.166,89.403 105.65,89.887 105.65,90.053 C206.2@105.7,90.053 ; C204.1@106.2,76.3 v1(106.928,76.3) ; C198.1@106.95,88.55 v1(106.949,89.251) ; C202.1@107.025,91.653 v1(107.025,92.825) ; C201.1@107.75,88.55 v1(107.75,89.278) ; v1(108.6,91.175) C193.2@108.6,91.903 ; C192.1@110.2,90.878 v1(111.378,90.878) ; v1(114.4,83.475) JP2.1@114.4,84.45
  other v1: 104.35,77.58 114.713,82.054 104.35,85.2 101.55,87.506 101.55,88.776
GND_CAN1: C121.2 C124.1 C125.1 C127.1 C129.2 C132.1 J6.1 J6.3 R236.2 U18.9 U18.10 U18.11 U18.12 U18.15 U18.16 U20.5 U22.2 U22.8 U24.3 X32.1 | length 30.6
  Top Layer w0.5: U20.5@112.415,5.31 112.542,5.31 112.75,5.102 v1(112.75,4.55) ; v1(112.918,10.132) 112.926,10.124 113.891,10.124 C129.2@113.9,10.115 ; v1(113.569,11.604) 114.396,11.604 115.3,10.7 C124.1@115.3,10.1 ; U22.2@114.905,3.995 116.142,3.995 116.397,4.25 v1(116.45,4.25) ; U22.8@120.161,5.315 120.523,5.315 120.7,5.492 v1(120.7,6.05)
  Bottom Layer w0.25: v1(115.125,12.925) U24.3@115.95,12.925
  Bottom Layer w0.5: v1@113.569,11.604 U18.9@114.949,11.604 ; U18.16@114.75,2.77 115.104,2.77 115.279,2.595 115.279,2.241 115.67,1.85 v1(116.4,1.85) ; U18.15@114.943,3.992 116.142,3.992 116.399,4.25 v1(116.45,4.25) 116.515,4.315 C121.2@117.15,4.315 ; U18.11@114.95,9.065 114.905,9.11 113.5,9.11 113.25,9.36 R236.2@111.8,9.36 ; U18.10@114.95,10.39 113.27,10.39 113.012,10.132 v1(112.918,10.132) 112.875,10.09 111.975,10.09 111.8,9.915 R236.2@111.8,9.36 ; v1@116.367,7.833 116.354,7.819 116.338,7.835 113.55,7.835 112.69,8.695 112.175,8.695 111.8,9.07 R236.2@111.8,9.36 ; v1(118.35,2.1) C125.1@118.35,3.25 ; v1(118.65,1.45) C127.1@119.7,1.45 ; v1(120.7,6.05) 121.282,6.05 121.575,6.343 121.575,6.575 C132.1@121.8,6.8
  other v1: 116.4,7.8
GND_CAN2: C122.2 C123.1 C126.1 C128.1 C130.2 C131.1 J6.5 J6.7 R240.2 U19.9 U19.10 U19.11 U19.12 U19.15 U19.16 U21.5 U23.2 U23.8 U25.3 X33.1 | length 26.6
  Top Layer w0.25: U23.2@103.8,18.93 105.38,18.93 v1(105.4,18.95)
  Top Layer w0.5: U21.5@101.181,17.695 101.181,17.623 101.301,17.503 101.301,16.749 v1(101.7,16.35) ; v1(102.3,22.5) C130.2@103,22.5 ; v1(102.469,24.044) 103.401,24.044 104.2,23.245 104.2,22.512 C123.1@104.212,22.5 ; v1(107.9,20.2) U23.8@109.261,20.2 ; v1(108.25,14.45) C128.1@108.25,15.15
  Bottom Layer w0.25: v1(115.075,24.25) U25.3@115.9,24.25
  Bottom Layer w0.5: R240.2@100.7,15.2 100.745,15.155 U19.16@103.85,15.155 v1(105.231,15.156) ; v1@102.47,24.045 U19.9@103.85,24.045 ; U19.15@103.81,16.4 103.822,16.412 105.19,16.412 v1(105.202,16.4) ; U19.12@103.815,20.25 103.822,20.242 105.195,20.242 v1(105.202,20.25) ; U19.11@103.85,21.505 102.615,21.505 102.3,21.82 v1(102.3,22.5) 102.333,22.5 102.608,22.775 U19.10@103.85,22.775 ; v1(106.05,15.875) C122.2@106.05,16.7 ; X33.1@106.7,23.8 C131.1@108.7,23.8 ; C126.1@107.6,15.625 107.7,15.625 108.225,15.1 108.225,15 108.25,14.975 v1(108.25,14.45)
GPIO1: M1.206 R9.1 U3.20 X6.1 | length 30.3
  Top Layer w0.25: M1.206@65.5,65.6 65.5,67.4 v1(66,67.9)
  L1-Signal w0.15: v1(66,67.9) 67.25,69.15 68.85,69.15 71.6,71.9 76.05,71.9 77.35,70.6 77.35,70.238 77.663,69.925 78.625,69.925 v1(79.3,69.25)
  L2-Signal w0.15: v1(79.3,69.25) 81.55,71.5 81.55,72.7 83.75,74.9 X6.1@85.15,74.9
  Bottom Layer w0.25: U3.20@77.15,69.95 77.2,70 77.662,70 77.694,69.968 78.806,69.968 R9.1@78.838,70 79.3,69.538 v1(79.3,69.25)
GPIOs.GPIO2: J2.8 M1.208 | length 18.3
  Top Layer w0.15: v1(59.4,62.7) 60.858,62.7 61.233,62.325 63.299,62.325 63.674,62.7 63.883,62.7 64.827,63.644 65.044,63.644 65.988,64.588 65.988,65.588 M1.208@66,65.6
  L1-Signal w0.15: J2.8@57.805,53.775 58.8,54.77 58.8,57.8 59.425,58.425 59.425,59.125 59.425,62.675 v1(59.4,62.7)
GPIOs.GPIO3: J2.10 M1.210 | length 17.5
  Top Layer w0.15: v1(60,62.15) 60.983,62.15 61.183,61.95 63.558,61.95 64.858,63.25 65.2,63.25 66.5,64.55 M1.210@66.5,65.6
  L1-Signal w0.15: J2.10@59.075,53.775 59.075,54.099 59.075,54.621 59.1,54.645 59.1,57.676 59.6,58.176 59.725,58.301 59.725,59.249 59.725,61.875 v1(60,62.15)
GPIOs.GPIO4: M1.212 R11.1 U6.1 X11.1 | length 15.8
  Top Layer w0.15: v1(59.05,68.95) 59.063,68.95 59.563,69.45 65.2,69.45 67,67.65 M1.212@67,65.6
  Bottom Layer w0.15: X11.1@54.35,68.651 54.611,68.911 R11.1@55.817,68.911 55.847,68.941 U6.1@57.556,68.941 57.561,68.946 59.046,68.946 v1(59.05,68.95)
I2C1_SCL: J2.13 M1.14 R140.1 R229.2 U5.6 U7.2 X10.1 | length 155.8
  Top Layer w0.15: U7.2@3.4,56.4 3.85,56.4 4.05,56.6 4.05,57.95 2.4,59.6 2.4,63.45 7.55,68.6 14.45,68.6 v1@15,68.05 ; v1(14.9,67.95) v1@15,68.05 ; M1.14@15.5,65.6 15.5,67.55 v1@15,68.05 ; X10.1@60.7,102.5 60.7,101.475 61.725,100.45 61.725,100.025 62,99.75 U5.6@62.4,99.75
  L2-Signal w0.15: v1(38.15,75.4) 40.6,72.95 40.6,71.474 41.724,70.35 42.426,70.35 43.15,71.074 43.15,77.676 45.75,80.276 45.75,83.524 53.95,91.724 53.95,98.75 55.251,100.051 55.251,100.794 55.631,101.173 56.373,101.173 57.8,102.6 60.6,102.6 X10.1@60.7,102.5
  L3-Signal w0.15: v1(38.15,75.4) 39.2,74.35 39.2,71.776 44.751,66.225 53.049,66.225 64.4,54.874 64.4,52.716 63.413,51.73 62.39,51.73 J2.13@61.615,52.505
  Bottom Layer w0.15: v1(14.9,67.95) 15.35,67.5 15.35,67.038 15.788,66.6 22.226,66.6 28.476,72.85 34.95,72.85 36.75,74.65 37.85,74.65 38.15,74.95 v1(38.15,75.4) 38.15,75.85 38.45,76.15 41.9,76.15 42.45,76.7 R140.1@43.2,76.7
  Bottom Layer w0.25: v1(38.15,75.4) R229.2@39.25,75.4
I2C1_SCL_MPCIe: R136.1 R142.1 U31.6 | length 37.3
  Top Layer w0.15: R136.1@50.9,101.85 50.925,101.875 U31.6@52.58,101.875 53.775,101.875 v1(53.8,101.9)
  L2-Signal w0.15: v1(42.15,73.9) 41.55,74.5 41.55,76.15 41.8,76.4 41.8,77.623 44.85,80.673 44.85,83.897 52.9,91.947 52.9,101 v1(53.8,101.9)
  Bottom Layer w0.25: v1(42.15,73.9) R142.1@43.25,73.9
I2C1_SDA: J2.15 M1.12 R147.1 R230.2 U5.5 U7.1 X9.1 | length 157.8
  Top Layer w0.15: U7.1@3.4,55.9 3.9,55.9 4.35,56.35 4.35,58.1 2.7,59.75 2.7,63.326 7.374,68 13.798,68 v1(14.58,67.218) 15,66.798 M1.12@15,65.6 ; U5.5@62.4,100.25 62.4,101.4 X9.1@63.5,102.5
  L2-Signal w0.15: v1(38.15,72.4) 37.45,73.1 37.45,74.05 37.9,74.5 38.6,74.5 40.15,72.95 40.15,71.5 41.6,70.05 42.55,70.05 43.45,70.95 43.45,77.551 48.549,82.65 49,82.65 49.35,83 49.35,86.7 54.3,91.65 54.3,98.676 55.551,99.927 55.551,100.669 55.755,100.873 61.873,100.873 X9.1@63.288,102.288
  L3-Signal w0.15: v1(38.15,72.4) 44.625,65.925 52.925,65.925 64.1,54.75 64.1,52.841 63.764,52.505 J2.15@62.885,52.505
  Bottom Layer w0.15: v1(14.58,67.218) 15.498,66.3 22.35,66.3 28.45,72.4 v1(38.15,72.4) 38.15,72 36.35,70.2 36.35,69.3 37.4,68.25 41.85,68.25 R147.1@43.2,69.6
  Bottom Layer w0.25: v1(38.15,72.4) R230.2@39.25,72.4
I2C1_SDA_MPCIe: R137.1 R143.1 U31.5 | length 38.4
  Top Layer w0.15: U31.5@52.58,102.525 52.58,103.93 R137.1@52.6,103.95
  L2-Signal w0.15: v1(42.15,72.4) 41.25,73.3 41.25,75.95 41.25,76.274 41.5,76.524 41.5,77.747 44.55,80.797 44.55,84.021 52.6,92.071 v1(52.6,103.2)
  Bottom Layer w0.25: v1(42.15,72.4) R143.1@43.25,72.4
I2C4_SCL: J2.14 M1.95 R183.1 U47.3 X64.1 | length 67.9
  Top Layer w0.15: M1.95@35.75,57.4 35.75,56.088 35.838,56 40.774,56 42.25,54.524 42.25,53.7 X64.1@43.25,52.7
  L2-Signal w0.15: X64.1@43.25,52.7 44.15,53.6 46.508,53.6 46.558,53.65 46.583,53.625 47.017,53.625 47.042,53.65 47.092,53.6 50.1,53.6 53.8,57.3 58.09,57.3 59.765,55.625 60.117,55.625 60.425,55.317 60.425,54.965 J2.14@61.615,53.775 62.39,54.55 66.467,54.55 75.517,45.5 v1(87.55,45.5)
  Bottom Layer w0.15: R183.1@88.3,45.5 v1(87.55,45.5) 87.05,45.5 86.65,45.9 86.65,46.75 86.95,47.05 87.899,47.05 88.225,47.376 88.225,47.925 U47.3@88.35,48.05
I2C4_SCL_3V3: R181.1 R251.1 R257.1 U43.6 U45.6 U47.6 | length 49.3
  Top Layer w0.15: v1(94.831,59.369) 96.294,59.369 R251.1@96.6,59.063
  Top Layer w0.25: v1(94.831,82.659) 94.846,82.659 95.152,82.353 R257.1@96.6,82.353
  L2-Signal w0.15: v1(94.831,59.369) 95.8,60.338 95.8,81.69 v1(94.831,82.659)
  Bottom Layer w0.15: R181.1@85.5,50.745 86.755,50.745 87.125,50.375 88.175,50.375 88.35,50.55 U47.6@88.35,51.59 88.35,52.75 88.15,52.95 88.15,53.6 89.55,55 95.1,55 95.65,55.55 95.65,58.55 v1(94.831,59.369)
  Bottom Layer w0.25: U43.6@93.45,59.368 v1@94.83,59.368 ; U45.6@93.45,82.658 v1(94.831,82.659)
I2C4_SDA: J2.16 M1.93 R184.1 U47.4 X65.1 | length 71.6
  Top Layer w0.15: M1.93@35.25,57.4 35.25,56.1 35.65,55.7 40.65,55.7 41.95,54.4 41.95,51.4 X65.1@43.25,50.1
  L2-Signal w0.15: X65.1@43.25,50.1 43.275,50.075 50.283,50.075 50.333,50.025 50.767,50.025 50.817,50.075 52.55,50.075 52.74,49.885 61.785,49.885 63.75,51.85 63.75,52.91 J2.16@62.885,53.775 66.818,53.775 75.972,44.62 v1(87.568,44.62)
  Bottom Layer w0.15: U47.4@87.7,48.05 87.663,48.013 87.363,48.013 86.25,46.9 86.25,45.35 86.98,44.62 v1(87.568,44.62) R184.1@88.3,44.62
I2C4_SDA_3V3: R180.1 R252.1 R258.1 U43.3 U45.3 U47.5 | length 42.7
  Top Layer w0.15: v1(94.831,55.559) 95.704,55.559 95.935,55.328 96.225,55.328 96.6,54.953 R252.1@96.6,54.663
  Top Layer w0.25: v1(94.831,78.849) 95.704,78.849 95.935,78.618 96.225,78.618 96.6,78.243 R258.1@96.6,77.953
  L2-Signal w0.15: v1(94.831,55.559) 94.14,56.25 94.14,62.39 95.5,63.75 95.5,78.18 v1(94.831,78.849)
  Bottom Layer w0.15: R180.1@85.5,51.745 86.305,51.745 86.46,51.59 U47.5@87.7,51.59 87.7,53.65 89.608,55.558 U43.3@93.45,55.558
  Bottom Layer w0.25: U43.3@93.45,55.558 v1@94.83,55.558 ; U45.3@93.45,78.848 v1(94.831,78.849)
I2C_3.I2C3_SCL: M1.59 R224.1 R232.2 | length 28
  Top Layer w0.15: M1.59@26.75,57.4 26.75,58.578 26.9,58.728 v1(26.9,59.3)
  L2-Signal w0.15: v1(26.9,59.3) 26.9,61.75 27.95,62.8 27.95,66.142 29.708,67.9 36.15,67.9 38.75,70.5 38.75,73.3 v1(38.15,73.9)
  Bottom Layer w0.25: R224.1@37.4,73.2 37.4,73.8 37.5,73.9 v1(38.15,73.9) R232.2@39.25,73.9
I2C_3.I2C3_SDA: M1.57 R85.1 R231.2 | length 24.2
  Top Layer w0.15: M1.57@26.25,57.4 v1(26.25,59.8)
  L2-Signal w0.15: v1(26.25,59.8) 26.25,61.708 27.65,63.108 27.65,66.267 29.583,68.2 35.55,68.2 v1(37.15,69.8)
  Bottom Layer w0.25: v1(37.15,69.8) 38.25,70.9 R231.2@39.25,70.9 R85.1@39.25,69.65
I2C_PCIE_SCL: R145.1 R229.1 R232.1 U31.3 | length 39.5
  Top Layer w0.15: v1(54.966,103.275) 54.947,103.256 54.947,102.003 55.075,101.875 U31.3@56.12,101.875
  L2-Signal w0.15: v1(42.1,75.4) 42.1,77.499 45.15,80.549 45.15,83.773 53.35,91.973 53.35,99.35 54.651,100.651 54.651,101.042 54.966,101.357 v1(54.966,103.275)
  Bottom Layer w0.15: R232.1@40.95,73.9 R229.1@40.95,75.4 v1(42.1,75.4) R145.1@43.25,75.4
I2C_PCIE_SDA: R144.1 R230.1 R231.1 U31.4 | length 42.8
  Top Layer w0.15: v1(56.102,103.275) 56.12,103.257 U31.4@56.12,102.525
  L2-Signal w0.15: v1(42.1,70.9) 42.823,71.623 42.823,77.773 45.45,80.4 45.45,83.649 53.65,91.849 53.65,99.226 54.951,100.527 54.951,100.918 55.4,101.367 55.4,102.573 v1(56.102,103.275)
  Bottom Layer w0.15: R230.1@40.95,72.4 R231.1@40.95,70.9 v1(42.1,70.9) R144.1@43.25,70.9 R144.1@43.2,70.85
I2S_2_BCLK: M1.42 R209.1 | length 30.6
  Top Layer w0.15: R209.1@15.3,87.65 15.35,87.65 16.15,88.45 19.9,88.45 24.6,83.75 24.6,69.05 22.5,66.95 M1.42@22.5,65.6
JTAG1_TCK: J13.4 M1.9 U66.1 | length 34.6
  Top Layer w0.15: v1(13.15,59.9) 14.05,59 14.05,58.608 14.245,58.412 14.245,57.405 M1.9@14.25,57.4 ; v1(18.637,40.79) U66.1@18.637,39.675 18.637,39.36 17.01,37.733 17.01,34.49 17.82,33.68 J13.4@19.4,33.68
  L1-Signal w0.15: v1(13.15,59.9) 13.15,58.924 12.525,58.299 12.525,49.574 18.075,44.024 18.075,43.083 18.637,42.52 v1(18.637,40.79)
JTAG1_TDI: J13.8 M1.1@12.25,57.4 U67.1 | length 35.4
  Top Layer w0.15: v1(11.4,58.9) 11.446,58.854 11.796,58.854 12.238,58.412 12.238,57.412 M1.1@12.25,57.4 ; J13.8@19.4,36.22 20.82,36.22 21.7,37.1 21.7,38.15 22.25,38.7 U67.1@22.25,39.725 v1(22.25,40.84)
  L1-Signal w0.15: v1(11.4,58.9) 11.4,58.787 11.6,58.587 11.6,49.2 17.15,43.65 17.15,40.55 18.05,39.65 20.667,39.65 21.857,40.84 v1(22.25,40.84)
JTAG1_TDO: J13.6 M1.5 U66.3 | length 38.4
  Top Layer w0.15: v1@12.1,60.249 12.1,59.674 13.25,58.524 M1.5@13.25,57.4 ; J13.6@19.4,34.95 17.8,34.95 17.35,35.4 17.35,37.35 18.15,38.15 20.2,38.15 20.537,38.487 U66.3@20.537,39.675 20.6,39.738 v1(20.6,40.75)
  L1-Signal w0.15: v1(12.099,60.25) 12.099,59.375 12.225,59.249 12.225,49.449 17.775,43.899 17.775,40.91 18.42,40.265 19.015,40.265 19.5,40.75 v1(20.6,40.75)
JTAG1_TMS: J13.2 M1.13 U66.6 | length 37.3
  Top Layer w0.15: v1(13.95,60.15) 13.992,60.15 15.275,58.867 15.275,58.433 15.255,58.412 15.255,57.405 M1.13@15.25,57.4 ; v1(18.6,43.4) 18.6,42.222 U66.6@18.637,42.185 17.785,42.185 17.2,41.6 17.2,40.15 16.6,39.55 16.6,33.7 17.89,32.41 J13.2@19.4,32.41
  L1-Signal w0.15: v1(13.95,60.15) 13.95,59.3 12.825,58.175 12.825,49.698 18.578,43.945 18.578,43.422 v1(18.6,43.4)
JTAG1_TRST#: J13.10 M1.3 U67.6 | length 39.9
  Top Layer w0.15: v1(11.35,59.7) 11.436,59.614 11.636,59.614 12.75,58.5 M1.3@12.75,57.4 ; J13.10@19.4,37.49 20.94,37.49 21.35,37.9 21.35,41.02 22.25,41.92 U67.6@22.25,42.235 v1(22.25,43.35)
  L1-Signal w0.15: v1(11.35,59.7) 11.925,59.125 11.925,49.325 17.45,43.8 17.45,40.81 18.295,39.965 20.558,39.965 21.4,40.807 21.4,42.5 v1(22.25,43.35)
JTAG.JTAG1_VREF: J13.1 M1.7 U67.3 | length 42.4
  Top Layer w0.15: M1.7@13.75,57.4 13.75,58.5 12.6,59.65 12.6,60.092 13.208,60.7 14.2,60.7 v1(14.75,60.15) ; J13.1@23.3,32.41 24.12,32.41 24.689,32.979 24.737,32.979 25.025,33.267 25.025,37.875 24.15,38.75 U67.3@24.15,39.725 v1(24.15,40.84)
  L1-Signal w0.15: v1(14.75,60.15) 14.75,59.6 13.125,57.975 13.125,49.822 19.047,43.9 22.442,43.9 24.15,42.192 v1(24.15,40.84)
